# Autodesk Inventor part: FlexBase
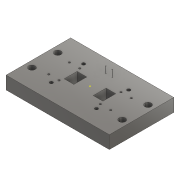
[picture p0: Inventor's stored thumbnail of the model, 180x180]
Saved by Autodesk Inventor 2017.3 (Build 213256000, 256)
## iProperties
Part Number: FlexBase
Material: ステンレス鋼
Document SubType Name: モデリング
Designer: kyushu-hep
Density: 8 g/cm^3
Appearance: 半つや出し
Sheet Metal Rule: Default
Mass: 5352.02 g
Surface Area: 367.335 cm^2
Volume: 277.307 cm^3
Author: kyushu-hep
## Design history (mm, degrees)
sketch "スケッチ1"
  geometry: L1 (-112, 0)-(112, 0) reference; L2 (0, -70)-(0, 70) reference; L3 (80, -50)-(-80, -50); L4 (-80, -50)-(-80, 50); L5 (-80, 50)-(80, 50); L6 (80, 50)-(80, -50); L7 (80, -50)-(-80, 50); L8 (-80, -50)-(80, 50); 1 further point
  constraints: 12 end point, 2 midpoint, 2 parallel, 1 horizontal, 1 perpendicular
  dimensions: "d0" = 160 distance of L4.end L5.end; "d1" = 100 distance of L3.end L4.end
extrude "押し出し1" new body sketch "スケッチ1" distance "d2" = 20; taper "d3" = 0 deg
sketch "スケッチ12"
  geometry: L1 (-80, 50)-(-80, -50) reference; L2 (-80, -50)-(80, -50) reference; C1 r 0.5 at (-5.05, 29.5); C2 r 0.5 at (5.05, 29.5); 1 further point
  constraints: 2 centre point
  dimensions: "d66" = 1 diameter of C1; "d67" = 1 diameter of C2; "d130" = 10.1 distance of C2.centre C1.centre; "d133" = 29.5 vertical distance of point (0, 0) C2.centre; "d134" = 5.05 horizontal distance of C1.centre point (0, 0)
extrude "押し出し9" join sketch "スケッチ12" distance "d72" = 10; taper "d73" = 0 deg
sketch "スケッチ18"
  geometry: L1 (-80, 50)-(-80, -50) reference; L2 (-15, -10)-(-30, -10); L3 (-30, -10)-(-30, 10); L4 (-30, 10)-(-15, 10); L5 (-15, 10)-(-15, -10); L6 (-15, -10)-(-30, 10); L7 (-30, -10)-(-15, 10); L8 (80, -50)-(80, 50) reference; L9 (15, -10)-(30, -10); L10 (30, -10)-(30, 10); L11 (30, 10)-(15, 10); L12 (15, 10)-(15, -10); L13 (15, -10)-(30, 10); L14 (30, -10)-(15, 10); L15 (-80, -50)-(80, -50) reference; 3 further points
  constraints: 24 end point, 4 midpoint, 4 parallel, 2 equal length, 2 horizontal, 2 perpendicular, 1 collinear
  dimensions: "d108" = 15 distance from line of point (0, 0) L5; "d109" = 20 distance of L4.end L2.start; "d135" = 10 distance from line of point (0, 0) L2; "d151" = 15 distance of L2.start L2.end; "d152" = 15 distance from line of L12 point (0, 0)
extrude "押し出し15" cut sketch "スケッチ18" distance "d111" = 30; taper "d112" = 0 deg
sketch "スケッチ22"
  geometry: 1 further point
sketch "スケッチ23"
  geometry: C1 r 5 at (-70, -20); C2 r 5 at (-70, 20); C3 r 5 at (70, 20); C4 r 5 at (70, -20); 1 further point
  constraints: 4 centre point
  dimensions: "d181" = 10 diameter of C1; "d182" = 10 diameter of C2; "d183" = 10 diameter of C3; "d184" = 10 diameter of C4
sketch "スケッチ24"
  geometry: C1 r 2.5 at (-35, 25); C2 r 2.5 at (35, 25); C3 r 2.5 at (-35, -25); C4 r 2.5 at (35, -25); 2 further points
  constraints: 4 centre point, 1 coincident
  dimensions: "d159" = 5 diameter of C1; "d160" = 25 vertical distance of C1.centre point (0, 0); "d161" = 35 horizontal distance of C1.centre point (0, 0); "d162" = 5 diameter of C2; "d163" = 35 horizontal distance of point (0, 0) C2.centre; "d164" = 25 vertical distance of C2.centre point (0, 0); "d165" = 5 diameter of C3; "d166" = 25 vertical distance of point (0, 0) C3.centre; "d167" = 35 horizontal distance of point (0, 0) C3.centre; "d168" = 5 diameter of C4; "d169" = 25 vertical distance of point (0, 0) C4.centre; "d170" = 35 horizontal distance of point (0, 0) C4.centre
extrude "押し出し19" cut sketch "スケッチ24" distance "d171" = 20; taper "d172" = 0 deg
feature "ねじ4" dims "d173" = 10, "d174" = 0
feature "ねじ5" dims "d175" = 10, "d176" = 0
feature "ねじ6" dims "d177" = 10, "d178" = 0
feature "ねじ7" dims "d179" = 10, "d180" = 0
extrude "押し出し20" cut sketch "スケッチ23" distance "d185" = 10; taper "d186" = 0 deg
sketch "スケッチ25"
  geometry: L1 (20, 20)-(-20, 20); L2 (-20, 20)-(-20, -20); L3 (-20, -20)-(20, -20); L4 (20, -20)-(20, 20); L5 (20, 20)-(-20, -20); L6 (-20, 20)-(20, -20); C1 r 1.5 at (-48, -16); C2 r 1.5 at (-48, 16); C3 r 1.5 at (-32, -16); C4 r 1.5 at (-32, 16); C5 r 1.5 at (-16, -16); C6 r 1.5 at (-16, 16); C7 r 1.5 at (0, -16); C8 r 1.5 at (0, 16); C9 r 1.5 at (16, -16); C10 r 1.5 at (16, 16); C11 r 1.5 at (32, -16); C12 r 1.5 at (32, 16); C13 r 1.5 at (48, -16); C14 r 1.5 at (48, 16); 2 further points
  constraints: 14 centre point, 12 end point, 2 horizontal, 2 midpoint, 2 parallel, 1 perpendicular, 1 vertical, 26 other
  dimensions: "d191" = 3 diameter of C1; "d192" = 48 horizontal distance of point (0, 0) C1.centre; "d193" = 16 vertical distance of point (0, 0) C1.centre; "d194" = 40 distance of L3.end L2.end; "d195" = 40 distance of L2.end L1.end; "d196" = 32 distance of C1.centre C2.centre; "d197" = 16 distance of C1.centre C3.centre
extrude "押し出し21" cut sketch "スケッチ25" distance "d198" = 20; taper "d199" = 0 deg
node "ソリッド1"
other parameters: "Thickness" = 0.5, "Kファクター" = 4.4, "BendRadius" = 0.5 (= Thickness), "BendReliefWidth" = 0.5 (= Thickness), "BendReliefDepth" = 0.25 (= 0.5 x Thickness), "CornerReliefSize" = 2 (= 4 x Thickness), "SeamGap" = 0.01, "MinimumRemnant" = 1 (= 2 x Thickness), "TransitionRadius" = 0.5 (= BendRadius), "JacobiRadiusSize" = 0.5 (= Thickness), "GapSize" = 0.5 (= Thickness)
